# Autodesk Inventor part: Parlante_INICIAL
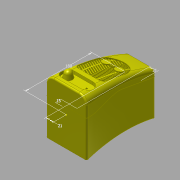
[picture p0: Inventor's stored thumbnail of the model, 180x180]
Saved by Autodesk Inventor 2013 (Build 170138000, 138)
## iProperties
Created: 2013-03
Part Number: Parlante_INICIAL
Material: Polycarbonate, Clear
Document SubType Name: Modeling
Designer: julian.chica
Density: 1 g/cm^3
Author: julian.chica
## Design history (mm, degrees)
sketch "Sketch2"
  geometry: L1 (55, 75)-(-55, 75); L2 (-55, 75)-(-55, -75); L3 (-55, -75)-(55, -75); L4 (55, -75)-(55, 75); L5 (55, 75)-(-55, -75); L6 (-55, 75)-(55, -75); 1 further point
  constraints: 12 end point, 2 midpoint, 2 parallel, 1 horizontal, 1 perpendicular
  dimensions: "d0" = 150 distance of L3.end L1.start; "d2" = 110 distance of L1.start L1.end
sketch "Sketch3"
  geometry: A1 r 500 centre (0, -425) between (200, 33.258) and (0, 75); 3 further points
  constraints: 2 point on circle, 1 centre point, 1 vertical alignment
  dimensions: "d3" = 500 radius of A1; "d5" = 200 horizontal distance of point (0, 0) A1.start
sketch "Sketch4"
  geometry: L1 (0, 0)-(200, -17.498); L2 (0, 0)-(0, -219.032); 2 further points
  constraints: 4 end point, 1 coincident, 1 vertical, 1 vertical alignment
  dimensions: "d6" = 85 deg angle of L2 L1
workplane "Work Plane1"
sketch "Sketch5"
  geometry: L1 (-40, 50.755)-(40, 50.755); L2 (40, 50.755)-(40, -64.245); L3 (40, -64.245)-(-40, -64.245); L4 (-40, -64.245)-(-40, 50.755); 3 further points
  constraints: 8 end point, 2 parallel, 1 horizontal, 1 midpoint, 1 perpendicular
  dimensions: "d7" = 115 distance between parallel lines of L3 L1; "d10" = 80 distance of L1.start L1.end; "d11" = 40 distance from line of point (0, 0) L4
loft "Loft1" sketch "Sketch5" dims "d12" = 0, "d13" = 90 deg, "d14" = 0, "d15" = 90 deg, "d16" = 0, "d17" = 90 deg
sketch "Sketch6"
  geometry: L1 (210, 13.258)-(104.31, 38.532); L2 (74.895, 38.152)-(33.172, 27.026); L3 (17.712, 25)-(-10, 25); L4 (200, 33.258)-(200, -81.742) reference; L5 (0, 75)-(0, -75) reference; A1 r 60 centre (90.355, -19.822) between (104.31, 38.532) and (74.895, 38.152); A2 r 60 centre (17.712, 85) between (17.712, 25) and (33.172, 27.026); 1 further point
  constraints: 6 end point, 4 point on circle, 4 tangent, 2 centre point, 1 equal radius, 1 horizontal
  dimensions: "d20" = 60 radius of A1; "d21" = 10 distance from line of L1.start L4; "d22" = 10 distance from line of L3.end L5; "d23" = 20 vertical distance of L4.start L1.start; "d24" = 50 vertical distance of L5.start L3.end
extrude_surface "ExtrusionSrf1" dims "d29" = 131.5, "d30" = 0
fillet "Fillet1" dims "d25" = 21.25, "d26" = 10, "d27" = 21.25, "d28" = 10
fillet "Fillet2" dims "d31" = 4
fillet "Fillet3" dims "d32" = 2
shell "Shell2" dims "d176" = 2.5
split "Split2"
  body "Solid1"
feature "Lip3" dims "d177" = 1.9, "d178" = 1.22, "d179" = 0, "d180" = 0.12217, "d181" = 0.12217, "d182" = 1.3
feature "Lip4" dims "d183" = 2, "d184" = 1.2, "d185" = 0, "d186" = 0.06981, "d187" = 0, "d188" = 0.2
workplane "Work Plane2"
sketch "Sketch7"
  geometry: L1 (-25, 47)-(25, 47); L2 (25, 47)-(25, 13); L3 (25, 13)-(-25, 13); L4 (-25, 13)-(-25, 47); L5 (-25, 47)-(25, 13); L6 (25, 47)-(-25, 13); A1 r 17 centre (-25, 30) between (-25, 47) and (-25, 13); A2 r 17 centre (25, 30) between (25, 13) and (25, 47); 3 further points
  constraints: 12 end point, 5 midpoint, 4 point on circle, 2 centre point, 2 parallel, 1 horizontal, 1 perpendicular, 1 vertical alignment
  dimensions: "d54" = 17 radius of A1; "d56" = 50 distance of L1.start L1.end; "d57" = 13 distance from line of L3 point (0, 0)
feature "Rest4" sketch "Sketch7" dims "d189" = 5, "d190" = 0, "d191" = 0, "d192" = 0, "d193" = 0, "d194" = 10 deg, "d195" = 1
workplane "Work Plane3"
sketch "Sketch8"
  geometry: L1 (25, 14)-(-25, 14) reference; 4 further points
  constraints: 1 horizontal alignment, 1 vertical alignment
  dimensions: "d73" = 180 vertical distance of point (-21, 180) point (0, 0); "d74" = 21 horizontal distance of point (-21, 180) point (0, 0); "d75" = 21 horizontal distance of point (0, 29) point (21, 180); "d196" = 15 distance from line of L1 point (0, 29)
feature "Boss3" dims "d197" = 0, "d198" = 0, "d199" = 8, "d200" = 3, "d201" = 9.5, "d202" = 1.5 deg, "d203" = 1 deg, "d206" = 2, "d207" = 2, "d208" = 5, "d209" = 0, "d210" = 9 deg, "d211" = 1.5 deg, "d212" = 0.25, "d213" = 0, "d214" = 0, "d215" = 360 deg
feature "Boss4" dims "d216" = 0, "d217" = 0, "d218" = 9, "d219" = 2, "d220" = 0.5, "d221" = 8.1, "d222" = 1.25, "d223" = 3.5, "d224" = 2.5 deg, "d225" = 2.5 deg, "d226" = 2.5 deg, "d227" = 2.5 deg, "d228" = 90 deg, "d231" = 1.5, "d232" = 2, "d233" = 5, "d234" = 0, "d235" = 9 deg, "d236" = 1 deg, "d237" = 0.25, "d238" = 0, "d239" = 0, "d240" = 360 deg
workplane "Work Plane4"
sketch "Sketch9" dims "d131" = 10, "d154" = 10
  geometry: L1 (-37.5, 120)-(37.5, 120); L2 (37.5, 120)-(37.5, 70); L3 (27.5, 60)-(-27.5, 60); L4 (-37.5, 70)-(-37.5, 120); L5 (-37.5, 120)-(37.5, 60); L6 (37.5, 120)-(-37.5, 60); L7 (0, 49.71)-(0, 187.485); L8 (-47.214, 175.937)-(0, 152.413); L9 (-47.214, 169.937)-(0, 146.413); L10 (-47.214, 163.937)-(0, 140.413); L11 (-47.214, 157.937)-(0, 134.413); L12 (-47.214, 151.937)-(0, 128.413); L13 (-47.214, 145.937)-(0, 122.413); L14 (-47.214, 139.937)-(0, 116.413); L15 (-47.214, 133.937)-(0, 110.413); L16 (-47.214, 127.937)-(0, 104.413); L17 (-47.214, 121.937)-(0, 98.413); L18 (-47.214, 115.937)-(0, 92.413); L19 (-47.214, 109.937)-(0, 86.413); L20 (-47.214, 103.937)-(0, 80.413); L21 (-47.214, 97.937)-(0, 74.413); L22 (47.214, 175.937)-(0, 152.413); L23 (47.214, 169.937)-(0, 146.413); L24 (47.214, 151.937)-(0, 128.413); L25 (47.214, 145.937)-(0, 122.413); L26 (47.214, 139.937)-(0, 116.413); L27 (47.214, 133.937)-(0, 110.413); L28 (47.214, 163.937)-(0, 140.413); L29 (47.214, 157.937)-(0, 134.413); L30 (47.214, 127.937)-(0, 104.413); L31 (47.214, 121.937)-(0, 98.413); L32 (47.214, 109.937)-(0, 86.413); L33 (47.214, 103.937)-(0, 80.413); L34 (47.214, 115.937)-(0, 92.413); L35 (47.214, 97.937)-(0, 74.413); L36 (-21, 168.94)-(-21, 53.316); L37 (21, 168.94)-(21, 53.316); L38 (-47.214, 91.937)-(0, 68.413); L39 (47.214, 91.937)-(0, 68.413); L40 (-47.214, 85.937)-(0, 62.413); L41 (47.214, 85.937)-(0, 62.413); L42 (-47.214, 79.937)-(0, 56.413); L43 (47.214, 79.937)-(0, 56.413); L44 (-47.214, 73.937)-(0, 50.413); L45 (47.214, 73.937)-(0, 50.413); L46 (-7.717, 126.838)-(0, 122.994); L47 (-7.577, 125.17)-(0, 121.395); L48 (0, 121.395)-(7.577, 125.17); L49 (0, 122.994)-(7.717, 126.838); A1 r 37.5 centre (0, 120) between (37.5, 120) and (-37.5, 120); A2 r 10 centre (-27.5, 70) between (-37.5, 70) and (-27.5, 60); A3 r 10 centre (27.5, 70) between (27.5, 60) and (37.5, 70); A4 r 10 centre (-17.577, 125.17) between (-7.717, 126.838) and (-7.577, 125.17); A5 r 10 centre (17.577, 125.17) between (7.577, 125.17) and (7.717, 126.838); 5 further points
  constraints: 98 end point, 19 symmetric about line, 10 point on circle, 8 point on line, 7 parallel, 5 centre point, 4 midpoint, 4 tangent, 3 vertical, 1 equal radius, 1 horizontal, 1 perpendicular, 1 vertical alignment, 60 other
  dimensions: "d122" = 75 distance of L5.end L6.end; "d123" = 60 distance of L1.end L5.end; "d124" = 60 distance from line of point (0, 0) L3; "d125" = 10 radius of A2; "d128" = 6 distance of L8.start L9.start; "d133" = 21 distance from line of point (0, 0) L36; "d151" = 6 distance of L21.start L38.start; "d156" = 20 diameter of A4
feature "Grill3" sketch "Sketch9" dims "d241" = 4, "d242" = 0, "d243" = 1, "d244" = 3, "d245" = 2.5, "d246" = 4, "d247" = 0, "d248" = 0, "d249" = 2.5, "d250" = 0, "d251" = 0, "d252" = 0, "d253" = 300.09496
workplane "Work Plane6"
sketch "Sketch10"
  geometry: A1 r 16 centre (0, -16) between (0, 0) and (0, -32) reference; 1 further point
workplane "Work Plane5"
sketch "Sketch11"
  geometry: L1 (0, 0)-(-2, 0); L2 (-2, 0)-(-2, -3.353); L3 (-2, -3.353)-(0, -3.353); L4 (0, -3.353)-(0, 0); 1 further point
  constraints: 8 end point, 2 parallel, 1 horizontal, 1 perpendicular
  dimensions: "d171" = 2 distance between parallel lines of L4 L2
revolve "Revolution3" sketch "Sketch11" stored, may be unused: angle "d256" = 90 deg
mirror "Mirror2"
sketch "Sketch13"
  geometry: L1 (-2, -1)-(-2, 0) reference; L2 (2, -1)-(2, 0) reference; L3 (-17, -1)-(17, -1) reference; L4 (0, -1)-(0, 19.543); L5 (-9.075, 12.181)-(-11.451, 0.902); L6 (-11.451, 0.902)-(-1.674, 0.902); L7 (-1.674, 0.902)-(-1.674, -1); L8 (0, -1)-(-1.674, -1); A1 r 9.274 centre (0, 10.269) between (0, 19.543) and (-9.075, 12.181); 1 further point
  constraints: 10 end point, 3 perpendicular, 2 point on circle, 2 point on line, 1 centre point, 1 collinear, 1 midpoint, 1 tangent
revolve "Revolution4" sketch "Sketch13" stored, may be unused: angle "d257" = 90 deg
body "Srf2"
node "Perilla"
node "frontal"
node "trasero"
other parameters: "d46" = 64.5, "d72" = 6.75, "d121" = 76, "d254" = 4, "d255" = 2.5
